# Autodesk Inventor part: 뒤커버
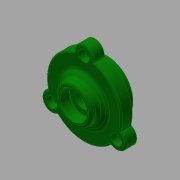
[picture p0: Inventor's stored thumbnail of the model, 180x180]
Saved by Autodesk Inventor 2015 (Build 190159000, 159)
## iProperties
Created: 2016-05
Part Number: 뒤커버
Document SubType Name: Modeling
Designer: mduedu
Density: 2.71 g/cm^3
Material: 알루미늄 6061
Appearance: 진녹색
Author: mduedu
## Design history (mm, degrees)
sketch "스케치1"
  geometry: C1 r 20 at (0, 0); C2 r 27.5 at (0, 0); 1 further point
  constraints: 2 centre point, 2 coincident
  dimensions: "d33" = 55 diameter of C2; "d34" = 40 diameter of C1
extrude "돌출1" new body sketch "스케치1" distance "d0" = 8; taper "d1" = 0 deg
extrude "돌출2" join sketch "스케치1" distance "d2" = 8; taper "d3" = 0 deg; dims "d35" = 9, "d36" = 0
sketch "스케치5"
  geometry: L1 (-27.5, 8)-(27.5, 8) reference; L2 (0, 0)-(0, 15); L3 (-27.5, 0)-(27.5, 0) reference; L4 (17.5, 8)-(0, 8); A1 r 25.375 centre (0, -10.375) between (17.5, 8) and (0, 15)
  constraints: 4 end point, 3 point on line, 2 point on circle, 1 centre point, 1 midpoint, 1 perpendicular
  dimensions: "d37" = 17.5 distance from line of L2 L4.start; "d39" = 7 distance from line of L1 L2.end
revolve "회전2" sketch "스케치5" stored, may be unused: angle "d40" = 90 deg
node "작업 평면1"
sketch "스케치6"
  geometry: C1 r 13.5 at (0, 0); 1 further point
  constraints: 1 centre point, 1 coincident
  dimensions: "d42" = 27 diameter of C1
extrude "돌출4" join sketch "스케치6" stored distance "d43" = 10; taper "d44" = 0 deg
sketch "스케치4"
  geometry: L1 (0, -9)-(0, 16); L2 (-15, -9)-(-15, 0); L3 (-15, 0)-(-10, 0); L4 (-10, 0)-(-10, 3); L5 (-10, 3)-(-6, 3); L6 (-6, 3)-(-6, 8.6); L7 (-6, 8.6)-(-10, 8.6); L8 (-10, 8.6)-(-10, 16); L9 (20, -9)-(-20, -9) reference; L10 (-13.5, 16)-(13.5, 16) reference; 1 further point
  constraints: 16 end point, 6 parallel, 3 point on line, 2 midpoint, 1 perpendicular, 1 vertical
  dimensions: "d15" = 30 diameter of L2 L1; "d16" = 20 diameter of L8 L1; "d18" = 9 distance of L2.start L2.end; "d19" = 3 distance of L3.end L4.end; "d20" = 20 diameter of L4 L1; "d21" = 12 diameter of L6 L1; "d45" = 7.4 distance of L7.end L8.end
revolve "회전1" sketch "스케치4" stored, may be unused: angle "d22" = 90 deg
fillet "모깎기2" dims "d23" = 3
fillet "모깎기3" dims "d24" = 0.3
chamfer "모따기2" distance "d46" = 1; stored, may be unused: second distance "d47" = 2, angle "d48" = 45 deg
fillet "모깎기4" dims "d49" = 3
fillet "모깎기5" dims "d50" = 2
sketch "스케치7"
  geometry: C1 r 7 at (0, 27.5); 2 further points
  constraints: 3 vertical alignment, 1 centre point, 2 other
  dimensions: "d54" = 14 diameter of C1
extrude "돌출5" join sketch "스케치7" stored distance "d55" = 10; taper "d56" = 0 deg
fillet "모깎기6" dims "d57" = 1
fillet "모깎기7" dims "d61" = 1
sketch "스케치8" dims "d62" = 55 (derived)
  geometry: C1 r 18.661 at (0, 0) reference; A1 r 2 centre (-7.999, 27.355) between (-7.437, 25.435) and (-5.999, 27.391) reference; A2 r 26.5 centre (0, 0) between (-7.437, 25.435) and (-25.746, -6.277) reference; A3 r 2 centre (-27.689, -6.75) between (-26.721, -8.5) and (-25.746, -6.277) reference; A4 r 6 centre (-23.816, -13.75) between (-26.721, -8.5) and (-20.722, -18.891) reference; A5 r 2 centre (-19.69, -20.604) between (-18.309, -19.158) and (-20.722, -18.891) reference; A6 r 26.5 centre (0, 0) between (-18.309, -19.158) and (18.309, -19.158) reference; A7 r 2 centre (19.69, -20.604) between (20.722, -18.891) and (18.309, -19.158) reference; A8 r 6 centre (23.816, -13.75) between (20.722, -18.891) and (26.721, -8.5) reference; A9 r 2 centre (27.689, -6.75) between (25.746, -6.277) and (26.721, -8.5) reference; A10 r 26.5 centre (0, 0) between (25.746, -6.277) and (7.437, 25.435) reference; A11 r 2 centre (7.999, 27.355) between (5.999, 27.391) and (7.437, 25.435) reference; A12 r 6 centre (0, 27.5) between (5.999, 27.391) and (-5.999, 27.391) reference; 4 further points
  constraints: 2 coincident, 1 vertical alignment, 6 other
  dimensions: "d65" = 360 deg dimension on A2.centre point (0, 27.5) (derived)
sketch "스케치9"
  geometry: 3 further points
  constraints: 3 other
hole "구멍2" sketch "스케치9" at (-23.816, -13.75), (23.816, -13.75), (0, 27.5) diameter "d67" = 4.5; stored, may be unused: countersink angle "d71" = 90 deg, drill point angle "d73" = 0 deg; dims "d68" = 6, "d69" = 8, "d70" = 4.6, "d72" = 8
chamfer "모따기3" distance "d76" = 0.7; stored, may be unused: second distance "d77" = 2, angle "d78" = 30 deg
node "솔리드1"
pattern_circular "원형 패턴1" dims angle "d59" = 360 deg
other parameters: "d41" = 8
